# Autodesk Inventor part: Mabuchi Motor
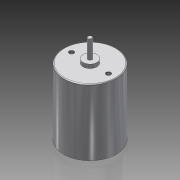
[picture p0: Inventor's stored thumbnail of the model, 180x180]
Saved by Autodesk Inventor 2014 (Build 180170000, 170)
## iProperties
Created: 2015-07
Part Number: Mabuchi Motor
Material: Generic
Document SubType Name: Modeling
Designer: Brad Factor
Density: 1 g/cm^3
Appearance: Aluminum - Polished
Author: Brad Factor
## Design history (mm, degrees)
sketch "Sketch1"
  geometry: L1 (-12.097, 0)-(-3.194, 0); L2 (-3.194, 0)-(-3.194, 1.765); L3 (-3.194, 1.765)-(-0.997, 1.765); L4 (-0.997, 1.765)-(-0.997, 10.274); L5 (-0.997, 10.274)-(0, 10.274); L6 (0, 10.274)-(0, -31.902); L7 (0, -31.902)-(-3.239, -31.902); L8 (-3.239, -31.902)-(-3.239, -29.553); L9 (-3.239, -29.553)-(-11.589, -29.553); L10 (-11.589, -29.553)-(-11.589, -30.48); L11 (-11.589, -30.48)-(-12.097, -30.48); L12 (-12.097, -30.48)-(-12.097, 0); 1 further point
  constraints: 24 end point, 6 horizontal, 6 vertical, 1 horizontal alignment, 1 vertical alignment
  dimensions: "d0" = 12.09675 distance between parallel lines of L6 L12; "d1" = 3.19405 distance between parallel lines of L6 L2; "d2" = 0.99695 distance between parallel lines of L6 L4; "d3" = 10.2743 distance between parallel lines of L1 L5; "d4" = 1.7653 distance of L1.end L2.end; "d5" = 30.48 distance of L11.end L1.start; "d6" = 0.508 distance of L10.end L11.end; "d7" = 3.2385 distance between parallel lines of L6 L8; "d8" = 2.3495 distance of L7.end L8.end; "d9" = 0.9271 distance of L9.end L10.end
revolve "Motor" sketch "Sketch1" stored, may be unused: angle "d10" = 90 deg
sketch "Hole Reference Sketch" dims "d11" = 2.54, "d12" = 2.54
  geometry: L1 (-7.239, 0)-(7.239, 0); C1 r 3.194 at (0, 0) reference; C2 r 12.097 at (0, 0) reference; 6 further points
  constraints: 4 coincident, 4 horizontal alignment, 2 end point, 1 horizontal, 1 midpoint, 4 other
  dimensions: "d13" = 14.478 distance of L1.end L1.start
sketch "Sketch3"
  geometry: 4 further points
  constraints: 2 coincident
  dimensions: "d23" = 17.018 distance of point (8.509, 0) point (-8.509, 0) (derived)
hole "#4-40 Tapped Holes" sketch "Sketch3" at (-8.509, 0), (8.509, 0) diameter "d14" = 2.159; stored, may be unused: countersink angle "d18" = 82 deg, drill point angle "d20" = 0 deg; dims "d15" = 19.05, "d16" = 5.5626, "d17" = 2.8448, "d19" = 4.826
fillet "1/64\" Fillet" dims "d21" = 0.39687
fillet "10 mil Fillet" dims "d22" = 0.254
body "Solid1"
